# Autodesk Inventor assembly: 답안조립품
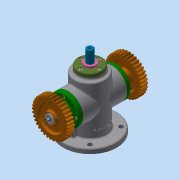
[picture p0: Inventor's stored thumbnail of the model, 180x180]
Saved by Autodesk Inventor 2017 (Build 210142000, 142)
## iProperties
Part Number: 답안조립품
Material: 일반
Document SubType Name: Assembly
Designer: mrc
Author: mrc
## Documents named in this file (17)
- C:\Users\mrc\Desktop\600606V1007\답안조립품.iam
- C:\Users\mrc\Desktop\600606V1007\본체.ipt
- C:\Users\mrc\Desktop\600606V1007\Ű 4x4x12.ipt
- C:\Users\mrc\Desktop\600606V1007\가변스프링.ipt
- C:\Users\mrc\Desktop\600606V1007\멈춤링.ipt
- C:\Users\mrc\Desktop\600606V1007\베어링 6203.ipt
- C:\Users\mrc\Desktop\600606V1007\볼트 M4.ipt
- C:\Users\mrc\Desktop\600606V1007\부시.ipt
- C:\Users\mrc\Desktop\600606V1007\스퍼기어.ipt
- C:\Users\mrc\Desktop\600606V1007\스프링와셔.ipt
- C:\Users\mrc\Desktop\600606V1007\스프링조립용 와셔.ipt
- C:\Users\mrc\Desktop\600606V1007\슬라이더.ipt
- C:\Users\mrc\Desktop\600606V1007\오일 실 17 30 8.ipt
- C:\Users\mrc\Desktop\600606V1007\커버 A.ipt
- C:\Users\mrc\Desktop\600606V1007\커버 B.ipt
- C:\Users\mrc\Desktop\600606V1007\편심축.ipt
- C:\Users\mrc\Desktop\600606V1007\평와셔.ipt
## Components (3 placed, 2 different names)
1. Ű 4x4x12:1
2. 가변스프링:1 — 각도:4
3. Ű 4x4x12:2
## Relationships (1: Angle 1)
- 각도:4 [Angle]: 가변스프링:1
